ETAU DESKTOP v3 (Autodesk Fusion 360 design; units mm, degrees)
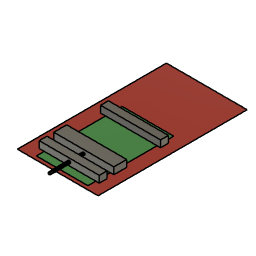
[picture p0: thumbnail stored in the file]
parameter "MORS_FIXE_BORD_AVANT" = 215
parameter "OUVERTURE" = 100
parameter "MORS_MOBILE_NOIX_SERRAGE" = 20
sketch "Esquisse1" plane through (0, 0, 0) normal (0, 0, 1) x axis (1, 0, 0)
  line L1 (119.0625, -219.8088) -> (-119.0625, -219.8088)
  line L2 (119.0625, 219.9287) -> (119.0625, -219.8088)
  line L3 (-119.0625, 219.9287) -> (119.0625, 219.9287)
  line L4 (-119.0625, -219.8088) -> (-119.0625, 219.9287)
  point P2 (-119.0625, -219.8088)
  point P5 (-119.0625, 219.9287)
  point P4 (119.0625, 219.9287)
  point P1 (0, 0)
  horizontal L1
  vertical L2
  horizontal L3
  vertical L4
  dimension "d1" distance P2 P5 = 439.7375
  dimension "d2" distance P4 P5 = 238.125
  dimension "d3" distance P1 P2 = 219.8088
  dimension "d4" distance P1 P2 = 119.0625
surface_patch "Correction de surface" sketch "Esquisse1"
sketch "Esquisse2" plane through (0, 0, 0) normal (0, 0, 1) x axis (1, 0, 0)
  line L1 (-73.7625, 44.0312) -> (78.2375, 44.0312)
  line L2 (-73.7625, -208.9688) -> (-73.7625, 44.0312)
  line L3 (78.2375, -208.9688) -> (-73.7625, -208.9688)
  line L4 (78.2375, 44.0312) -> (78.2375, -208.9688)
  point P1 (0, 0)
  point P2 (78.2375, 44.0312)
  point P3 (-73.7625, 44.0312)
  point P4 (-73.7625, -208.9688)
  horizontal L1
  vertical L2
  horizontal L3
  vertical L4
  dimension "d5" distance P1 P2 = 78.2375
  dimension "d6" distance P1 P2 = 44.0312
  dimension "d7" distance P2 P3 = 152
  dimension "d8" distance P3 P4 = 253
split_face "ScinderLesFaces"
component_from_bodies "Corps->Comp"
sketch "Esquisse1" plane through (0, 0, 0) normal (1, 0, 0) x axis (0, 1, 0)
  line L1 (-4.8088, 20) -> (18.1912, 20)
  line L2 (-4.8088, 0) -> (-4.8088, 20)
  line L3 (18.1912, 0) -> (-4.8088, 0)
  line L4 (18.1912, 20) -> (18.1912, 0)
  line L5 (22.5, 0) -> (1.75, 0)
  line L6 (-219.8088, 0) -> (-219.8088, 0)
  line L7 (-142.8088, 20) -> (-104.8088, 20)
  line L8 (-142.8088, 0) -> (-142.8088, 20)
  line L9 (-104.8088, 0) -> (-142.8088, 0)
  line L10 (-104.8088, 20) -> (-104.8088, 0)
  line L11 (-185.8088, 20) -> (-162.8088, 20)
  line L12 (-185.8088, 0) -> (-185.8088, 20)
  line L13 (-162.8088, 0) -> (-185.8088, 0)
  line L14 (-162.8088, 20) -> (-162.8088, 0)
  point P2 (18.1912, 20)
  point P3 (-4.8088, 20)
  point P5 (18.1912, 0)
  point P4 (-4.8088, 0)
  point P10 (-104.8088, 20)
  point P11 (-142.8088, 20)
  point P12 (-142.8088, 0)
  point P14 (-162.8088, 20)
  point P17 (-162.8088, 0)
  point P15 (-185.8088, 20)
  horizontal L1
  vertical L2
  horizontal L3
  vertical L4
  collinear L3 L5
  horizontal L7
  vertical L8
  horizontal L9
  vertical L10
  collinear L5 L9
  horizontal L11
  vertical L12
  horizontal L13
  vertical L14
  collinear L5 L13
  dimension "d9" distance P2 P3 = 23
  dimension "d10" distance P2 P5 = 20
  dimension "d11" distance P4 L6 = 215 (= "MORS_FIXE_BORD_AVANT")
  dimension "d15" distance L2 L10 = 100 (= "OUVERTURE")
  dimension "d16" distance P10 P11 = 38
  dimension "d17" distance P11 P12 = 20
  dimension "d18" distance P14 P17 = 20
  dimension "d19" distance P14 P15 = 23
  dimension "d20" distance L8 L14 = 20 (= "MORS_MOBILE_NOIX_SERRAGE")
extrude "Extrusion1" new body sketch "Esquisse1" profile of L1 L2 L3 L4 L5 L7 L8 L9 L10 L11 L12 L13 L14 distance 177
hole "Perçage" HoleDepth 23 HoleDiameter 6.7795 RefDim1 10 RefDim2 88.5 (= "( 177 / 2 ) * 1 mm")
work_plane "Plan de construction1" AlongDistance 0
sketch "Esquisse2" plane through (0, -142.8088, 0) normal (0, -1, 0) x axis (-1, 0, 0)
  line L1 (88.5, -20) -> (88.5, 0)
  line L2 (-88.5, -20) -> (88.5, -20)
  circle C1 centre (0, -10) radius 4
  point P2 (0, -10)
  dimension "d29" distance P2 L1 = 88.5 (= "( 177 / 2 ) * 1 mm")
  dimension "d30" distance P2 L2 = 10
  dimension "d31" diameter C1 = 8
extrude "Extrusion2" add sketch "Esquisse2" profile of C1 along normal blind 102
work_plane "Plan de construction2" AlongDistance 0
sketch "Esquisse3" plane through (0, -244.8088, 0) normal (0, -1, 0) x axis (-1, 0, 0)
  line L1 (-1.7321, -13) -> (-3.4641, -10)
  line L2 (1.7321, -13) -> (-1.7321, -13)
  line L3 (3.4641, -10) -> (1.7321, -13)
  line L4 (1.7321, -7) -> (3.4641, -10)
  line L5 (-1.7321, -7) -> (1.7321, -7)
  line L6 (-3.4641, -10) -> (-1.7321, -7)
  circle C1 centre (0, -10) radius 4
  point P8 (0, -10)
  point P9 (0, -10)
  coincident P8 P9
  dimension "d35" distance L2 L5 = 6
extrude "Extrusion3" cut sketch "Esquisse3" against normal blind 12
thread "Filetage2" ThreadOffset 0 ThreadLength 10
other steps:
base_feature "Fonction de base"
thread "Filetage1" ThreadOffset 0 ThreadDepth 10
create_component "CreateComponent1"
remove_body "RemoveBody1"
create_component "CreateComponent2"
